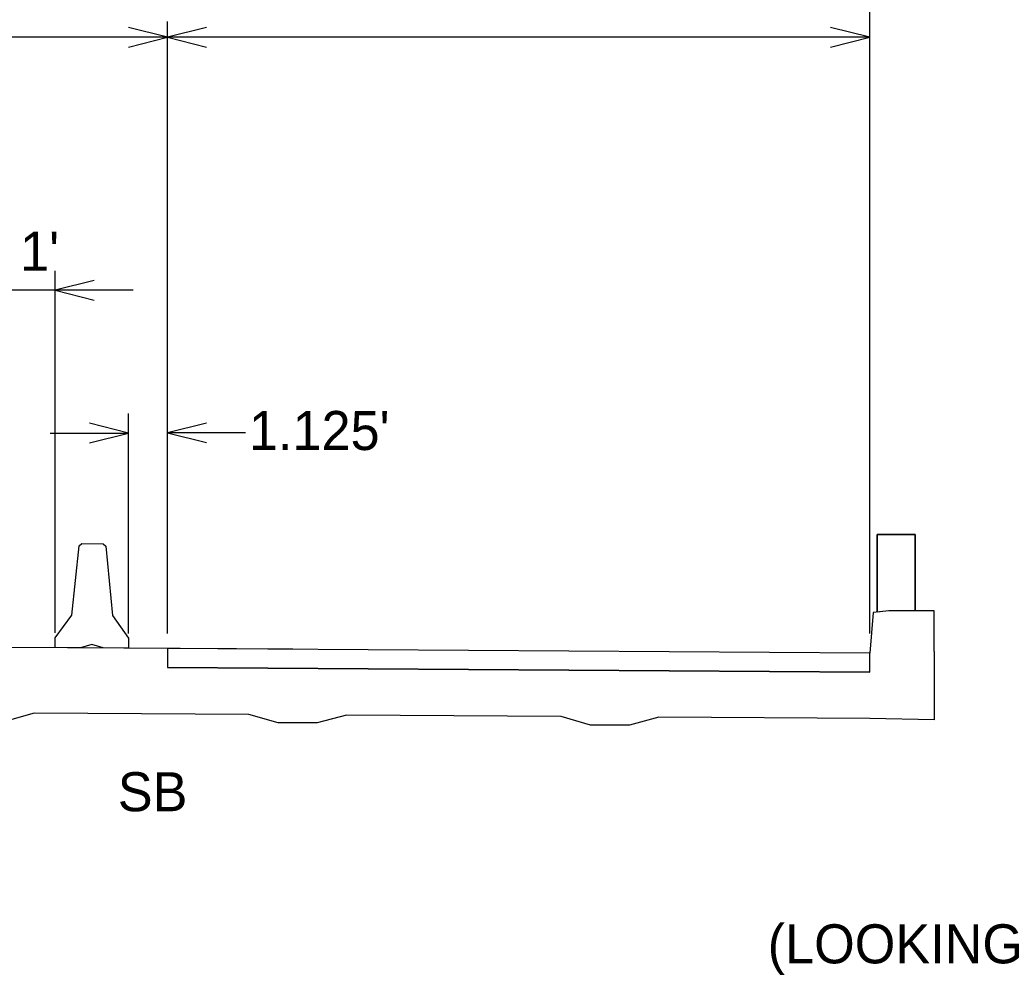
# Model space of a CAD drawing. Extents: x 10133 to 81668, y 7924 to 11018.
# Drawn here: x 11127 to 11636, y 9109 to 9598 of the extents above; entities that cross this region are included whole.
import ezdxf

# ---------------------------------------------------------------- set-up
doc = ezdxf.new("R2010")
doc.units = 0
for name, color, linetype in [('brgConcrete', 7, 'Continuous'), ('brgConstructionLines', 7, 'Continuous'), ('brgPreStructureExisting', 7, 'Continuous'), ('dsnStdLineDrawingWt2', 7, 'Continuous')]:
    doc.layers.add(name, color=color, linetype=linetype)

msp = doc.modelspace()

# ---------------------------------------------------------------- linework, layer by layer
at = {"layer": 'brgConcrete'}
for p, q in [((11202.55, 9276.34), (11202.51, 9266.55)), ((11562.25, 9273.93), (11202.55, 9276.34)), ((11562.25, 9264.14), (11562.25, 9273.93)), ((11562.23, 9264.14), (11202.51, 9266.55)), ((11562.25, 9264.14), (11202.55, 9266.55))]:
    msp.add_line(p, q, dxfattribs=at)
at = {"layer": 'brgConstructionLines'}
msp.add_circle((11266.71, 9276.02), 0.104, dxfattribs=at)
at = {"layer": 'brgPreStructureExisting'}
for p, q in [((11572.01, 9295.6), (11566.02, 9294.97)), ((11585.55, 9295.6), (11572.01, 9295.6)), ((11266.71, 9275.91), (11122.5, 9276.88)), ((11266.71, 9266.12), (11202.51, 9266.55)), ((11244.17, 9242.54), (11134.17, 9243.28)), ((11404.17, 9241.47), (11294.17, 9242.2)), ((11562.25, 9240.41), (11454.17, 9241.13))]:
    msp.add_line(p, q, dxfattribs=at)
for points in [[(11585.55, 9295.6), (11585.55, 9334.76), (11566.02, 9334.76), (11566.02, 9294.97)], [(11566.02, 9294.97), (11566.02, 9334.76), (11585.55, 9334.76), (11585.55, 9295.6)], [(11595.34, 9274.76), (11595.34, 9295.6), (11572.01, 9295.6), (11564.09, 9294.76), (11562.25, 9273.93)], [(11595.34, 9274.76), (11595.34, 9239.75), (11562.25, 9240.41)], [(11134.17, 9243.28), (11119.17, 9238.99), (11099.17, 9238.99), (11084.17, 9242.78)], [(11294.17, 9242.2), (11279.17, 9238.2), (11259.17, 9238.2), (11244.17, 9242.54)], [(11454.17, 9241.13), (11439.17, 9237.13), (11419.17, 9237.13), (11404.17, 9241.47)]]:
    msp.add_lwpolyline(points, dxfattribs=at)
for points in [[(11182.54, 9276.56), (11169.62, 9276.65), (11163.8, 9278.35), (11157.96, 9276.73), (11145.04, 9276.81), (11145.07, 9281.81), (11153.48, 9293.42), (11157.34, 9328.82), (11158.73, 9330.05), (11169.56, 9329.98), (11170.93, 9328.73), (11174.32, 9293.28), (11182.57, 9281.56)], [(11202.55, 9276.34), (11202.51, 9266.55), (11562.25, 9264.14), (11562.25, 9273.93)]]:
    msp.add_lwpolyline(points, close=True, dxfattribs=at)
at = {"layer": 'dsnStdLineDrawingWt2'}
for p, q in [((11562.25, 9283.93), (11562.25, 9672.18)), ((11202.52, 9284.06), (11202.52, 9597.48)), ((11562.25, 9283.93), (11562.25, 9599.33)), ((11202.51, 9589.33), (10492.25, 9589.33)), ((11562.25, 9589.33), (11202.51, 9589.33)), ((11145.02, 9284.37), (11145.02, 9469.77)), ((11165.02, 9464.77), (11145.02, 9459.77)), ((11165.06, 9459.77), (10492.25, 9459.77)), ((11185.02, 9459.77), (11145.02, 9459.77)), ((11145.02, 9459.77), (11165.02, 9454.77)), ((11182.52, 9284.06), (11182.52, 9396.65)), ((11142.52, 9386.65), (11182.52, 9386.65)), ((11242.52, 9386.77), (11202.52, 9386.77))]:
    msp.add_line(p, q, dxfattribs=at)
for points in [[(11182.52, 9584.33), (11202.52, 9589.33), (11182.52, 9594.33)], [(11222.52, 9594.33), (11202.52, 9589.33), (11222.52, 9584.33)], [(11542.25, 9584.33), (11562.25, 9589.33), (11542.25, 9594.33)], [(11162.52, 9381.65), (11182.52, 9386.65), (11162.52, 9391.65)], [(11222.52, 9391.77), (11202.52, 9386.77), (11222.52, 9381.77)]]:
    msp.add_lwpolyline(points, dxfattribs=at)

# ---------------------------------------------------------------- texts
for s, p in [("1'", (11127.04, 9469.77)), ("1.125'", (11244.28, 9377.96)), ('SB', (11177.09, 9192.96)), ('(LOOKING AHEAD STATION)', (11510.02, 9115.06))]:
    msp.add_text(s, height=20, dxfattribs=at).set_placement(p)

doc.saveas('drawing.dxf')
